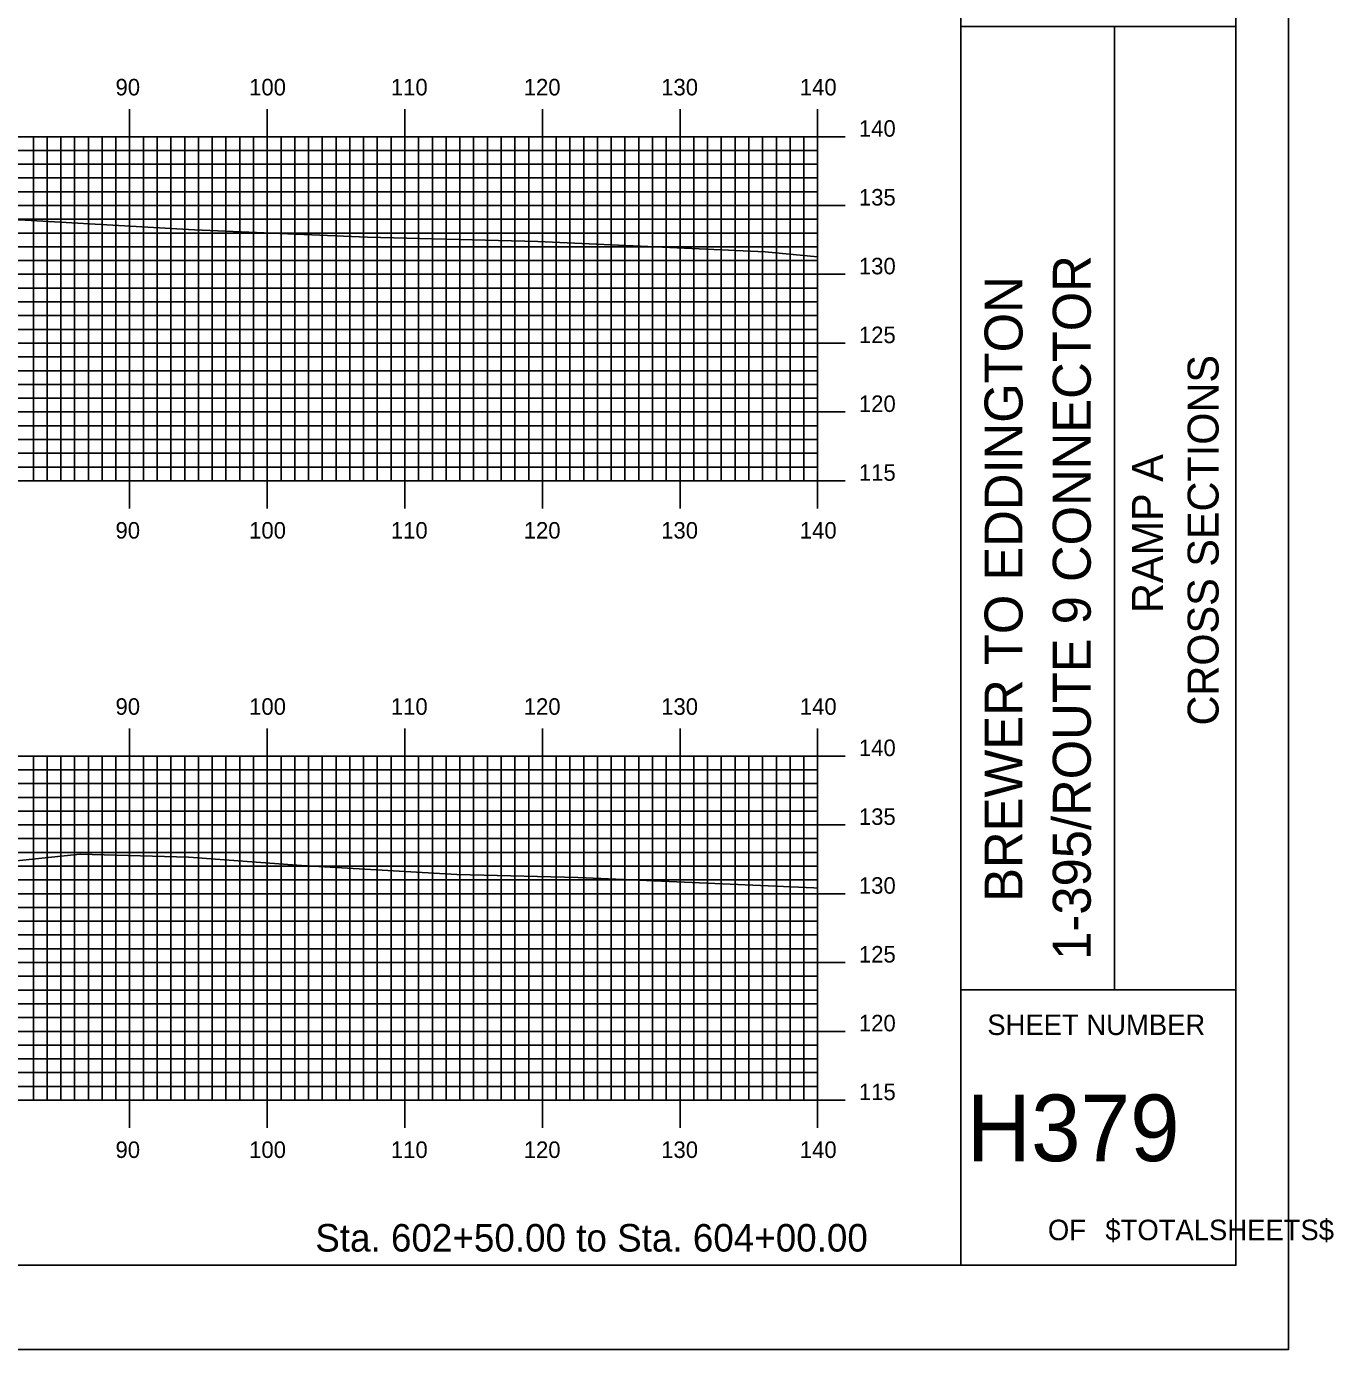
# Model space of a CAD drawing. Extents: x 841782 to 842125, y 363538 to 363758.
# Drawn here: x 842029.9 to 842124.9, y 363537.6 to 363633.7 of the extents above; entities that cross this region are included whole.
import ezdxf

# ---------------------------------------------------------------- set-up
doc = ezdxf.new("R2010")
doc.units = 0
for name, color, linetype in [('BORDER', 7, 'Continuous'), ('H_V ANNOTATION', 7, 'Continuous'), ('MAJOR', 7, 'Continuous'), ('MINOR', 7, 'Continuous'), ('PLOT BOUNDARY', 7, 'Continuous'), ('S_Roadway_Centerline', 7, 'Continuous')]:
    doc.layers.add(name, color=color, linetype=linetype)

msp = doc.modelspace()

# ---------------------------------------------------------------- linework, layer by layer
at = {"layer": 'BORDER'}
for p, q in [((842097.772, 363543.721), (842097.772, 363753.721)), ((842097.772, 363633.727), (842117.772, 363633.727)), ((842108.954, 363563.727), (842108.954, 363633.727)), ((842097.772, 363563.727), (842117.772, 363563.727))]:
    msp.add_line(p, q, dxfattribs=at)
msp.add_lwpolyline([(841797.772, 363543.721), (842117.772, 363543.721), (842117.772, 363753.721), (841797.772, 363753.721)], close=True, dxfattribs=at)
at = {"layer": 'MAJOR'}
for p, q in [((842037.372, 363627.725), (842037.372, 363625.721)), ((842047.372, 363627.725), (842047.372, 363625.721)), ((842057.372, 363627.725), (842057.372, 363625.721)), ((842067.372, 363627.725), (842067.372, 363625.721)), ((842077.372, 363627.725), (842077.372, 363625.721)), ((842087.372, 363627.725), (842087.372, 363625.721)), ((841807.372, 363625.721), (842087.372, 363625.721)), ((841807.372, 363625.721), (842087.372, 363625.721)), ((842037.372, 363600.721), (842037.372, 363625.721)), ((842047.372, 363600.721), (842047.372, 363625.721)), ((842057.372, 363600.721), (842057.372, 363625.721)), ((842067.372, 363600.721), (842067.372, 363625.721)), ((842077.372, 363600.721), (842077.372, 363625.721)), ((842089.376, 363625.721), (842085.368, 363625.721)), ((842087.372, 363600.721), (842087.372, 363625.721)), ((842087.372, 363600.721), (842087.372, 363625.721)), ((841807.372, 363620.721), (842087.372, 363620.721)), ((842089.376, 363620.721), (842085.368, 363620.721)), ((841807.372, 363615.721), (842087.372, 363615.721)), ((842089.376, 363615.721), (842085.368, 363615.721)), ((841807.372, 363610.721), (842087.372, 363610.721)), ((842089.376, 363610.721), (842085.368, 363610.721)), ((841807.372, 363605.721), (842087.372, 363605.721)), ((842089.376, 363605.721), (842085.368, 363605.721)), ((841807.372, 363600.721), (842087.372, 363600.721)), ((841807.372, 363600.721), (842087.372, 363600.721)), ((842037.372, 363598.717), (842037.372, 363600.721)), ((842047.372, 363598.717), (842047.372, 363600.721)), ((842057.372, 363598.717), (842057.372, 363600.721)), ((842067.372, 363598.717), (842067.372, 363600.721)), ((842077.372, 363598.717), (842077.372, 363600.721)), ((842089.376, 363600.721), (842085.368, 363600.721)), ((842087.372, 363598.717), (842087.372, 363600.721)), ((842037.372, 363582.725), (842037.372, 363580.721)), ((842047.372, 363582.725), (842047.372, 363580.721)), ((842057.372, 363582.725), (842057.372, 363580.721)), ((842067.372, 363582.725), (842067.372, 363580.721)), ((842077.372, 363582.725), (842077.372, 363580.721)), ((842087.372, 363582.725), (842087.372, 363580.721)), ((841807.372, 363580.721), (842087.372, 363580.721)), ((841807.372, 363580.721), (842087.372, 363580.721)), ((842037.372, 363555.721), (842037.372, 363580.721)), ((842047.372, 363555.721), (842047.372, 363580.721)), ((842057.372, 363555.721), (842057.372, 363580.721)), ((842067.372, 363555.721), (842067.372, 363580.721)), ((842077.372, 363555.721), (842077.372, 363580.721)), ((842089.376, 363580.721), (842085.368, 363580.721)), ((842087.372, 363555.721), (842087.372, 363580.721)), ((842087.372, 363555.721), (842087.372, 363580.721)), ((841807.372, 363575.721), (842087.372, 363575.721)), ((842089.376, 363575.721), (842085.368, 363575.721)), ((841807.372, 363570.721), (842087.372, 363570.721)), ((842089.376, 363570.721), (842085.368, 363570.721)), ((841807.372, 363565.721), (842087.372, 363565.721)), ((842089.376, 363565.721), (842085.368, 363565.721)), ((841807.372, 363560.721), (842087.372, 363560.721)), ((842089.376, 363560.721), (842085.368, 363560.721)), ((841807.372, 363555.721), (842087.372, 363555.721)), ((841807.372, 363555.721), (842087.372, 363555.721)), ((842037.372, 363553.717), (842037.372, 363555.721)), ((842047.372, 363553.717), (842047.372, 363555.721)), ((842057.372, 363553.717), (842057.372, 363555.721)), ((842067.372, 363553.717), (842067.372, 363555.721)), ((842077.372, 363553.717), (842077.372, 363555.721)), ((842089.376, 363555.721), (842085.368, 363555.721)), ((842087.372, 363553.717), (842087.372, 363555.721))]:
    msp.add_line(p, q, dxfattribs=at)
at = {"layer": 'MINOR'}
for p, q in [((842030.372, 363600.721), (842030.372, 363625.721)), ((842031.372, 363600.721), (842031.372, 363625.721)), ((842032.372, 363600.721), (842032.372, 363625.721)), ((842033.372, 363600.721), (842033.372, 363625.721)), ((842034.372, 363600.721), (842034.372, 363625.721)), ((842035.372, 363600.721), (842035.372, 363625.721)), ((842036.372, 363600.721), (842036.372, 363625.721)), ((842038.372, 363600.721), (842038.372, 363625.721)), ((842039.372, 363600.721), (842039.372, 363625.721)), ((842040.372, 363600.721), (842040.372, 363625.721)), ((842041.372, 363600.721), (842041.372, 363625.721)), ((842042.372, 363600.721), (842042.372, 363625.721)), ((842043.372, 363600.721), (842043.372, 363625.721)), ((842044.372, 363600.721), (842044.372, 363625.721)), ((842045.372, 363600.721), (842045.372, 363625.721)), ((842046.372, 363600.721), (842046.372, 363625.721)), ((842048.372, 363600.721), (842048.372, 363625.721)), ((842049.372, 363600.721), (842049.372, 363625.721)), ((842050.372, 363600.721), (842050.372, 363625.721)), ((842051.372, 363600.721), (842051.372, 363625.721)), ((842052.372, 363600.721), (842052.372, 363625.721)), ((842053.372, 363600.721), (842053.372, 363625.721)), ((842054.372, 363600.721), (842054.372, 363625.721)), ((842055.372, 363600.721), (842055.372, 363625.721)), ((842056.372, 363600.721), (842056.372, 363625.721)), ((842058.372, 363600.721), (842058.372, 363625.721)), ((842059.372, 363600.721), (842059.372, 363625.721)), ((842060.372, 363600.721), (842060.372, 363625.721)), ((842061.372, 363600.721), (842061.372, 363625.721)), ((842062.372, 363600.721), (842062.372, 363625.721)), ((842063.372, 363600.721), (842063.372, 363625.721)), ((842064.372, 363600.721), (842064.372, 363625.721)), ((842065.372, 363600.721), (842065.372, 363625.721)), ((842066.372, 363600.721), (842066.372, 363625.721)), ((842068.372, 363600.721), (842068.372, 363625.721)), ((842069.372, 363600.721), (842069.372, 363625.721)), ((842070.372, 363600.721), (842070.372, 363625.721)), ((842071.372, 363600.721), (842071.372, 363625.721)), ((842072.372, 363600.721), (842072.372, 363625.721)), ((842073.372, 363600.721), (842073.372, 363625.721)), ((842074.372, 363600.721), (842074.372, 363625.721)), ((842075.372, 363600.721), (842075.372, 363625.721)), ((842076.372, 363600.721), (842076.372, 363625.721)), ((842078.372, 363600.721), (842078.372, 363625.721)), ((842079.372, 363600.721), (842079.372, 363625.721)), ((842080.372, 363600.721), (842080.372, 363625.721)), ((842081.372, 363600.721), (842081.372, 363625.721)), ((842082.372, 363600.721), (842082.372, 363625.721)), ((842083.372, 363600.721), (842083.372, 363625.721)), ((842084.372, 363600.721), (842084.372, 363625.721)), ((842085.372, 363600.721), (842085.372, 363625.721)), ((842086.372, 363600.721), (842086.372, 363625.721)), ((841807.372, 363624.721), (842087.372, 363624.721)), ((842087.372, 363624.721), (842085.368, 363624.721)), ((841807.372, 363623.721), (842087.372, 363623.721)), ((842087.372, 363623.721), (842085.368, 363623.721)), ((841807.372, 363622.721), (842087.372, 363622.721)), ((842087.372, 363622.721), (842085.368, 363622.721)), ((841807.372, 363621.721), (842087.372, 363621.721)), ((842087.372, 363621.721), (842085.368, 363621.721)), ((841807.372, 363619.721), (842087.372, 363619.721)), ((842087.372, 363619.721), (842085.368, 363619.721)), ((841807.372, 363618.721), (842087.372, 363618.721)), ((842087.372, 363618.721), (842085.368, 363618.721)), ((841807.372, 363617.721), (842087.372, 363617.721)), ((842087.372, 363617.721), (842085.368, 363617.721)), ((841807.372, 363616.721), (842087.372, 363616.721)), ((842087.372, 363616.721), (842085.368, 363616.721)), ((841807.372, 363614.721), (842087.372, 363614.721)), ((842087.372, 363614.721), (842085.368, 363614.721)), ((841807.372, 363613.721), (842087.372, 363613.721)), ((842087.372, 363613.721), (842085.368, 363613.721)), ((841807.372, 363612.721), (842087.372, 363612.721)), ((842087.372, 363612.721), (842085.368, 363612.721)), ((841807.372, 363611.721), (842087.372, 363611.721)), ((842087.372, 363611.721), (842085.368, 363611.721)), ((841807.372, 363609.721), (842087.372, 363609.721)), ((842087.372, 363609.721), (842085.368, 363609.721)), ((841807.372, 363608.721), (842087.372, 363608.721)), ((842087.372, 363608.721), (842085.368, 363608.721)), ((841807.372, 363607.721), (842087.372, 363607.721)), ((842087.372, 363607.721), (842085.368, 363607.721)), ((841807.372, 363606.721), (842087.372, 363606.721)), ((842087.372, 363606.721), (842085.368, 363606.721)), ((841807.372, 363604.721), (842087.372, 363604.721)), ((842087.372, 363604.721), (842085.368, 363604.721)), ((841807.372, 363603.721), (842087.372, 363603.721)), ((842087.372, 363603.721), (842085.368, 363603.721)), ((841807.372, 363602.721), (842087.372, 363602.721)), ((842087.372, 363602.721), (842085.368, 363602.721)), ((841807.372, 363601.721), (842087.372, 363601.721)), ((842087.372, 363601.721), (842085.368, 363601.721)), ((842030.372, 363555.721), (842030.372, 363580.721)), ((842031.372, 363555.721), (842031.372, 363580.721)), ((842032.372, 363555.721), (842032.372, 363580.721)), ((842033.372, 363555.721), (842033.372, 363580.721)), ((842034.372, 363555.721), (842034.372, 363580.721)), ((842035.372, 363555.721), (842035.372, 363580.721)), ((842036.372, 363555.721), (842036.372, 363580.721)), ((842038.372, 363555.721), (842038.372, 363580.721)), ((842039.372, 363555.721), (842039.372, 363580.721)), ((842040.372, 363555.721), (842040.372, 363580.721)), ((842041.372, 363555.721), (842041.372, 363580.721)), ((842042.372, 363555.721), (842042.372, 363580.721)), ((842043.372, 363555.721), (842043.372, 363580.721)), ((842044.372, 363555.721), (842044.372, 363580.721)), ((842045.372, 363555.721), (842045.372, 363580.721)), ((842046.372, 363555.721), (842046.372, 363580.721)), ((842048.372, 363555.721), (842048.372, 363580.721)), ((842049.372, 363555.721), (842049.372, 363580.721)), ((842050.372, 363555.721), (842050.372, 363580.721)), ((842051.372, 363555.721), (842051.372, 363580.721)), ((842052.372, 363555.721), (842052.372, 363580.721)), ((842053.372, 363555.721), (842053.372, 363580.721)), ((842054.372, 363555.721), (842054.372, 363580.721)), ((842055.372, 363555.721), (842055.372, 363580.721)), ((842056.372, 363555.721), (842056.372, 363580.721)), ((842058.372, 363555.721), (842058.372, 363580.721)), ((842059.372, 363555.721), (842059.372, 363580.721)), ((842060.372, 363555.721), (842060.372, 363580.721)), ((842061.372, 363555.721), (842061.372, 363580.721)), ((842062.372, 363555.721), (842062.372, 363580.721)), ((842063.372, 363555.721), (842063.372, 363580.721)), ((842064.372, 363555.721), (842064.372, 363580.721)), ((842065.372, 363555.721), (842065.372, 363580.721)), ((842066.372, 363555.721), (842066.372, 363580.721)), ((842068.372, 363555.721), (842068.372, 363580.721)), ((842069.372, 363555.721), (842069.372, 363580.721)), ((842070.372, 363555.721), (842070.372, 363580.721)), ((842071.372, 363555.721), (842071.372, 363580.721)), ((842072.372, 363555.721), (842072.372, 363580.721)), ((842073.372, 363555.721), (842073.372, 363580.721)), ((842074.372, 363555.721), (842074.372, 363580.721)), ((842075.372, 363555.721), (842075.372, 363580.721)), ((842076.372, 363555.721), (842076.372, 363580.721)), ((842078.372, 363555.721), (842078.372, 363580.721)), ((842079.372, 363555.721), (842079.372, 363580.721)), ((842080.372, 363555.721), (842080.372, 363580.721)), ((842081.372, 363555.721), (842081.372, 363580.721)), ((842082.372, 363555.721), (842082.372, 363580.721)), ((842083.372, 363555.721), (842083.372, 363580.721)), ((842084.372, 363555.721), (842084.372, 363580.721)), ((842085.372, 363555.721), (842085.372, 363580.721)), ((842086.372, 363555.721), (842086.372, 363580.721)), ((841807.372, 363579.721), (842087.372, 363579.721)), ((842087.372, 363579.721), (842085.368, 363579.721)), ((841807.372, 363578.721), (842087.372, 363578.721)), ((842087.372, 363578.721), (842085.368, 363578.721)), ((841807.372, 363577.721), (842087.372, 363577.721)), ((842087.372, 363577.721), (842085.368, 363577.721)), ((841807.372, 363576.721), (842087.372, 363576.721)), ((842087.372, 363576.721), (842085.368, 363576.721)), ((841807.372, 363574.721), (842087.372, 363574.721)), ((842087.372, 363574.721), (842085.368, 363574.721)), ((841807.372, 363573.721), (842087.372, 363573.721)), ((842087.372, 363573.721), (842085.368, 363573.721)), ((841807.372, 363572.721), (842087.372, 363572.721)), ((842087.372, 363572.721), (842085.368, 363572.721)), ((841807.372, 363571.721), (842087.372, 363571.721)), ((842087.372, 363571.721), (842085.368, 363571.721)), ((841807.372, 363569.721), (842087.372, 363569.721)), ((842087.372, 363569.721), (842085.368, 363569.721)), ((841807.372, 363568.721), (842087.372, 363568.721)), ((842087.372, 363568.721), (842085.368, 363568.721)), ((841807.372, 363567.721), (842087.372, 363567.721)), ((842087.372, 363567.721), (842085.368, 363567.721)), ((841807.372, 363566.721), (842087.372, 363566.721)), ((842087.372, 363566.721), (842085.368, 363566.721)), ((841807.372, 363564.721), (842087.372, 363564.721)), ((842087.372, 363564.721), (842085.368, 363564.721)), ((841807.372, 363563.721), (842087.372, 363563.721)), ((842087.372, 363563.721), (842085.368, 363563.721)), ((841807.372, 363562.721), (842087.372, 363562.721)), ((842087.372, 363562.721), (842085.368, 363562.721)), ((841807.372, 363561.721), (842087.372, 363561.721)), ((842087.372, 363561.721), (842085.368, 363561.721)), ((841807.372, 363559.721), (842087.372, 363559.721)), ((842087.372, 363559.721), (842085.368, 363559.721)), ((841807.372, 363558.721), (842087.372, 363558.721)), ((842087.372, 363558.721), (842085.368, 363558.721)), ((841807.372, 363557.721), (842087.372, 363557.721)), ((842087.372, 363557.721), (842085.368, 363557.721)), ((841807.372, 363556.721), (842087.372, 363556.721)), ((842087.372, 363556.721), (842085.368, 363556.721))]:
    msp.add_line(p, q, dxfattribs=at)
at = {"layer": 'PLOT BOUNDARY'}
msp.add_lwpolyline([(841781.585, 363537.603), (842121.585, 363537.603), (842121.585, 363757.603), (841781.585, 363757.603)], close=True, dxfattribs=at)
at = {"layer": 'S_Roadway_Centerline'}
for points in [[(841935.358, 363615.194), (841938.117, 363615.234), (841938.822, 363615.265), (841951.305, 363615.687), (841954.445, 363615.699), (841955.175, 363615.744), (841958.675, 363615.3), (841963.903, 363614.586), (841976.148, 363612.85), (841977.39, 363612.639), (841990.914, 363610.364), (841991.988, 363610.403), (842004.055, 363615.079), (842010.509, 363617.704), (842015.685, 363618.798), (842026.394, 363619.448), (842028.855, 363619.68), (842029.789, 363619.65), (842042.082, 363618.964), (842048.29, 363618.678), (842054.647, 363618.429), (842067.042, 363618.102), (842083.57, 363617.344), (842087.372, 363617.004)], [(842024.963, 363572.671), (842033.778, 363573.589), (842041.637, 363573.372), (842049.87, 363572.771), (842061.147, 363572.109), (842069.939, 363571.902), (842087.087, 363571.14), (842087.372, 363571.126)]]:
    msp.add_lwpolyline(points, dxfattribs=at)

# ---------------------------------------------------------------- texts
at = {"layer": 'BORDER'}
for s, height, p in [('1-395/ROUTE 9 CONNECTOR', 2.75575, (842107.221, 363565.921)), ('BREWER TO EDDINGTON', 2.75575, (842102.261, 363570.13)), ('CROSS SECTIONS', 2.25, (842116.513, 363582.943)), ('RAMP A', 2.25, (842112.463, 363591.118))]:
    msp.add_text(s, height=height, rotation=90, dxfattribs=at).set_placement(p)
for s, height, p in [('SHEET NUMBER', 1.49054, (842099.703, 363560.454)), ('H379', 4.8388, (842098.211, 363551.286)), ('OF', 1.4905, (842104.106, 363545.547)), ('$TOTALSHEETS$', 1.49054, (842108.285, 363545.547))]:
    msp.add_text(s, height=height, dxfattribs=at).set_placement(p)
at = {"layer": 'H_V ANNOTATION'}
for s, height, p in [('90', 1.2, (842036.344, 363628.721)), ('100', 1.2, (842046.055, 363628.721)), ('110', 1.2, (842056.355, 363628.721)), ('120', 1.2, (842066.012, 363628.721)), ('130', 1.2, (842076.002, 363628.721)), ('140', 1.2, (842086.077, 363628.721)), ('140', 1.2, (842090.372, 363625.721)), ('135', 1.2, (842090.372, 363620.721)), ('130', 1.2, (842090.372, 363615.721)), ('125', 1.2, (842090.372, 363610.721)), ('120', 1.2, (842090.372, 363605.721)), ('115', 1.2, (842090.372, 363600.721)), ('90', 1.2, (842036.344, 363596.521)), ('100', 1.2, (842046.055, 363596.521)), ('110', 1.2, (842056.355, 363596.521)), ('120', 1.2, (842066.012, 363596.521)), ('130', 1.2, (842076.002, 363596.521)), ('140', 1.2, (842086.077, 363596.521)), ('90', 1.2, (842036.344, 363583.721)), ('100', 1.2, (842046.055, 363583.721)), ('110', 1.2, (842056.355, 363583.721)), ('120', 1.2, (842066.012, 363583.721)), ('130', 1.2, (842076.002, 363583.721)), ('140', 1.2, (842086.077, 363583.721)), ('140', 1.2, (842090.372, 363580.721)), ('135', 1.2, (842090.372, 363575.721)), ('130', 1.2, (842090.372, 363570.721)), ('125', 1.2, (842090.372, 363565.721)), ('120', 1.2, (842090.372, 363560.721)), ('115', 1.2, (842090.372, 363555.721)), ('90', 1.2, (842036.344, 363551.521)), ('100', 1.2, (842046.055, 363551.521)), ('110', 1.2, (842056.355, 363551.521)), ('120', 1.2, (842066.012, 363551.521)), ('130', 1.2, (842076.002, 363551.521)), ('140', 1.2, (842086.077, 363551.521)), ('Sta. 602+50.00 to Sta. 604+00.00', 2.0004, (842050.863, 363544.721))]:
    msp.add_text(s, height=height, dxfattribs=at).set_placement(p)

doc.saveas('drawing.dxf')
